(* Logix 5000 project; controller Hardy_1769_Sample_Program vendor 1 type 14 code 151 rev 30.11; software revision 30.02; part 3 of 5 *)
(* tags used below, declared in another part *)
   Default_Return_Float : HardyFloatWeight;   // Default Return Values With Weight In Foating Point Format
(* Hardy_HI1769_Scale_0, continued *)

ROUTINE Write_to_Non_Volatile   (* ladder *)
// Save Current Settings to Non-Volatile Memory
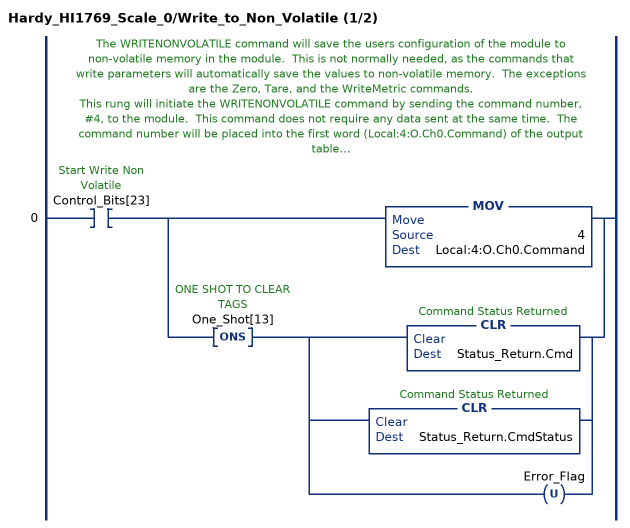
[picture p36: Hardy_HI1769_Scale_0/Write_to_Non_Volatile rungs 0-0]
   // The WRITENONVOLATILE command will save the users configuration of the module to non-volatile memory in the module.  This is not normally needed, as the commands that write parameters will automatically save the values to non-volatile memory.  The exceptions are the Zero, Tare, and the WriteMetric commands.
   // This rung will initiate the WRITENONVOLATILE command by sending the command number, #4, to the module.  This command does not require any data sent at the same time.  The command number will be placed into the first word (Local:4:O.Ch0.Command) of the output table.
   // Here the program will also clear the Status_Return tag and ERROR_FLAG of any previous values before running this command and receiving its return values.
   0: XIC(Control_Bits[23])[MOV(4,Local:4:O.Ch0.Command) ,ONS(One_Shot[13]) [CLR(Status_Return.Cmd) ,CLR(Status_Return.CmdStatus) ,OTU(Error_Flag) ] ];
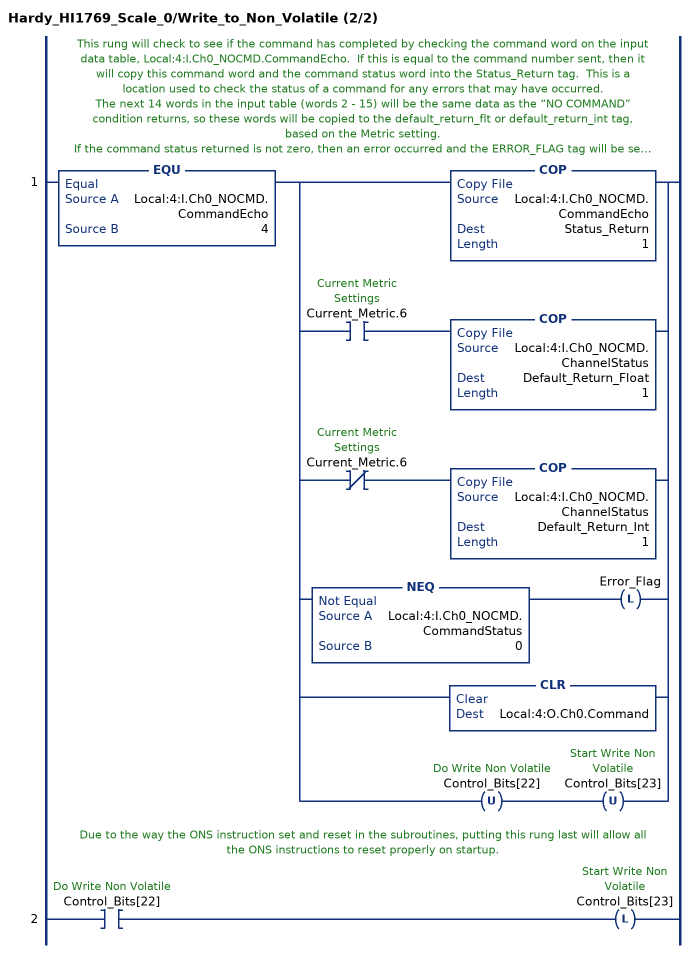
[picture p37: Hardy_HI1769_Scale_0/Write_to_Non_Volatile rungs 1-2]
   // This rung will check to see if the command has completed by checking the command word on the input data table, Local:4:I.Ch0_NOCMD.CommandEcho.  If this is equal to the command number sent, then it will copy this command word and the command status word into the Status_Return tag.  This is a location used to check the status of a command for any errors that may have occurred.
   // The next 14 words in the input table (words 2 - 15) will be the same data as the “NO COMMAND” condition returns, so these words will be copied to the default_return_flt or default_return_int tag, based on the Metric setting.
   // If the command status returned is not zero, then an error occurred and the ERROR_FLAG tag will be set high.  The user can monitor this bit to know if an error occurred and then check the Status_Return tag for the command and status return.
   // Finally, the command is cleared from the output table,Local:4:O.Ch0.Command, and any control bits are cleared.
   1: EQU(Local:4:I.Ch0_NOCMD.CommandEcho,4)[COP(Local:4:I.Ch0_NOCMD.CommandEcho,Status_Return,1) ,XIC(Current_Metric.6) COP(Local:4:I.Ch0_NOCMD.ChannelStatus,Default_Return_Float,1) ,XIO(Current_Metric.6) COP(Local:4:I.Ch0_NOCMD.ChannelStatus,Default_Return_Int,1) ,NEQ(Local:4:I.Ch0_NOCMD.CommandStatus,0) OTL(Error_Flag) ,CLR(Local:4:O.Ch0.Command) ,OTU(Control_Bits[22]) OTU(Control_Bits[23]) ];
   // Due to the way the ONS instruction set and reset in the subroutines, putting this rung last will allow all the ONS instructions to reset properly on startup.
   2: XIC(Control_Bits[22])OTL(Control_Bits[23]);
END_ROUTINE

ROUTINE Zero   (* ladder *)
// Zero Scale
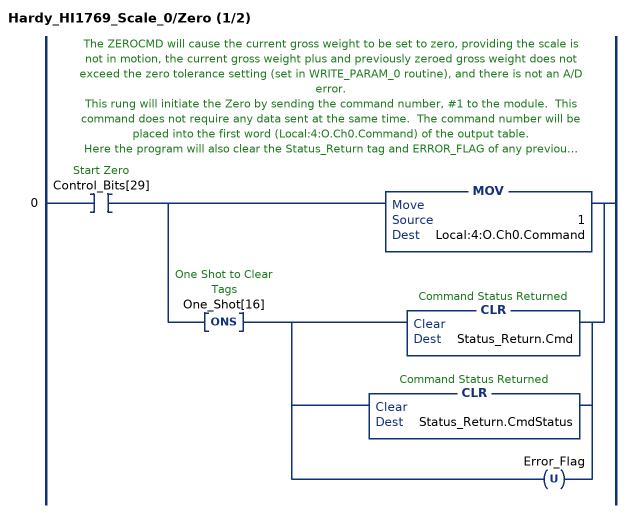
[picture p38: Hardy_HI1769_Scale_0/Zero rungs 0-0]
   // The ZEROCMD will cause the current gross weight to be set to zero, providing the scale is not in motion, the current gross weight plus and previously zeroed gross weight does not exceed the zero tolerance setting (set in WRITE_PARAM_0 routine), and there is not an A/D error.
   // This rung will initiate the Zero by sending the command number, #1 to the module.  This command does not require any data sent at the same time.  The command number will be placed into the first word (Local:4:O.Ch0.Command) of the output table.
   // Here the program will also clear the Status_Return tag and ERROR_FLAG of any previous values before running this command and receiving its return values.
   0: XIC(Control_Bits[29])[MOV(1,Local:4:O.Ch0.Command) ,ONS(One_Shot[16]) [CLR(Status_Return.Cmd) ,CLR(Status_Return.CmdStatus) ,OTU(Error_Flag) ] ];
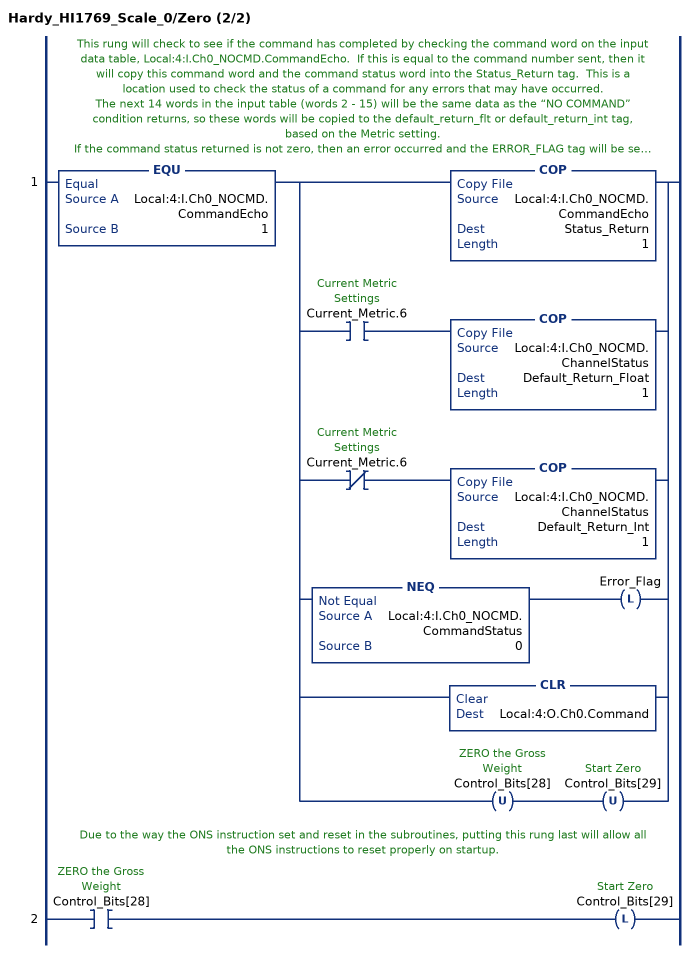
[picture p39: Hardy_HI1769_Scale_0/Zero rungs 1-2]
   // This rung will check to see if the command has completed by checking the command word on the input data table, Local:4:I.Ch0_NOCMD.CommandEcho.  If this is equal to the command number sent, then it will copy this command word and the command status word into the Status_Return tag.  This is a location used to check the status of a command for any errors that may have occurred.
   // The next 14 words in the input table (words 2 - 15) will be the same data as the “NO COMMAND” condition returns, so these words will be copied to the default_return_flt or default_return_int tag, based on the Metric setting.
   // If the command status returned is not zero, then an error occurred and the ERROR_FLAG tag will be set high.  The user can monitor this bit to know if an error occurred and then check the Status_Return tag for the command and status return.
   // Finally, the command is cleared from the output table, Local:4:O.Ch0.Command, and any control bits are cleared.
   1: EQU(Local:4:I.Ch0_NOCMD.CommandEcho,1)[COP(Local:4:I.Ch0_NOCMD.CommandEcho,Status_Return,1) ,XIC(Current_Metric.6) COP(Local:4:I.Ch0_NOCMD.ChannelStatus,Default_Return_Float,1) ,XIO(Current_Metric.6) COP(Local:4:I.Ch0_NOCMD.ChannelStatus,Default_Return_Int,1) ,NEQ(Local:4:I.Ch0_NOCMD.CommandStatus,0) OTL(Error_Flag) ,CLR(Local:4:O.Ch0.Command) ,OTU(Control_Bits[28]) OTU(Control_Bits[29]) ];
   // Due to the way the ONS instruction set and reset in the subroutines, putting this rung last will allow all the ONS instructions to reset properly on startup.
   2: XIC(Control_Bits[28])OTL(Control_Bits[29]);
END_ROUTINE
END_PROGRAM

PROGRAM Hardy_HI1769_Scale_1   (* main routine MainRoutine *)
VAR
   ADC_problem : BOOL;
   Control_Bits : BOOL[32] := ([30] := 1, [31] := 1);   // Control Bits For All Routines In This Program
        [11]   // Start Read Parameters 0
        [3]   // Start C2 Search
        [20]   // Do Write Metric
        [22]   // Do Write Non Volatile
        [10]   // Do Read Parameters 0
        [14]   // Do Read Serial Numbers
        [24]   // Do Write Parameters 0
        [16]   // Do Reload Non Volatile
        [26]   // Do Write Parameters 1
        [12]   // Do Read Parameters 1
        [23]   // Start Write Non Volatile
        [13]   // Start Read Parameters 1
        [21]   // Start Write Metric
        [7]   // Start CAL Low
        [19]   // Start Tare
        [29]   // Start Zero
        [1]   // Start C2 CAL
        [0]   // Do C2 CAL
        [5]   // Start CAL High
        [8]   // Set to Defaults
        [2]   // Do C2 Search
        [9]   // Start Defaults
        [15]   // Start Read Serial Numbers
        [25]   // Start Write Parameters 0
        [17]   // Start Reload Non Volatile
        [27]   // Starte Write Parameters 1
        [18]   // TARE the Net Weight
        [28]   // ZERO the Gross Weight
        [4]   // Do Traditional CAL HIGH
        [6]   // Do Traditional CAL LOW
   Control_Bits1 : BOOL[32];
        [4]   // Start Stability Test
        [3]   // Do Stability Test
        [5]   // Stop Stability Test
        [2]   // Read Test Data
        [1]   // Start IT Test
        [0]   // Do IT Test
   Current_Metric : INT := 2;   // Current Metric Settings
   Default_Return_Flt : HardyFloatWeight := (Channel_Status := 16#8040, Gross_Weight := -128.37949, Net_Weight := -128.37949, Metric := 16#0040, ADC_Counts := 1429576, Rate_of_Change := 514.0, Conv_Count := 32546);   // Default Return Values With Weight In Foating Point Format
   Default_Return_Int : HardyIntWeight := (Channel_Status := 16#8000, FirmwareRev := 16#0303, Metric := 16#0002, ADC_Counts := 2195901, Rate_of_Change := 1, Serial_Number := 4260, Conv_Count := 29766);   // Default Return Values With Weight In Integer Format
   Error_Flag : BOOL;
   Hardy_HI1769WS_Ch1_Channel_Status : INT := 16#8000;   // Ch1 Channel Status 16#0001 ADC Error 16#0002 AD Failure 16#0040 Motion 16#0080 Not Calibrated 16#0100 Eeprom Write 16#0200 Default Command Sent 16#8000 Ch Enabled
   Hardy_HI1769WS_Ch1_Command_Echo : INT;   // Ch1 Current Command Echo 16#0000 No Command 16#0001 Zero Command 16#0002 Tare Command 16#0003 Write Metric 16#0004 Write Non-Volatile 16#0010 Reload Non-Volatile 16#0064 Cal Low 16#0065 Cal High 16#0066 C2 Cal 16#0067 Write Param 0 16#0068 Write Param 1 16#0069 Read Param 0 16#006A Read Param 1 16#006B Stability Test 16#006C IT Test Results 16#006D Do IT Test 16#006E Search C2 16#006F IT Weigh Result 16#0070 C2 Serial 16#0094 Set Defaults 16#00FF Sofware Version
   Hardy_HI1769WS_Ch1_Command_Status : INT;   // Ch1 Current Command Status 0 Succes 1 ADC Error 2 ADC Failure 40 In Motion -3 Out of Tolerance -4 Out of Range -5 No Such Command -6 No C2 Device -7 C2 Unequal Caps -8 Hard Cal Not Enough Counts
   Hardy_HI1769WS_Ch1_Gross_Display_Float : REAL;   // Ch1 Gross Weight Float
   Hardy_HI1769WS_Ch1_Gross_Display_Int : DINT;   // Ch1 Gross Weight int
   Hardy_HI1769WS_Ch1_Last_Command : INT := 16#0064;   // Ch1 Last Command Sent 16#0000 No Command 16#0001 Zero Command 16#0002 Tare Command 16#0003 Write Metric 16#0004 Write Non-Volatile 16#0010 Reload Non-Volatile 16#0064 Cal Low 16#0065 Cal High 16#0066 C2 Cal 16#0067 Write Param 0 16#0068 Write Param 1 16#0069 Read Param 0 16#006A Read Param 1 16#006B Stability Test 16#006C IT Test Results 16#006D Do IT Test 16#006E Search C2 16#006F IT Weigh Result 16#0070 C2 Serial 16#0094 Set Defaults 16#00FF Sofware Version
   Hardy_HI1769WS_Ch1_Last_Command_Status : INT;   // Ch1 Last Command Status 0 Succes 1 ADC Error 2 ADC Failure 40 In Motion -3 Out of Tolerance -4 Out of Range -5 No Such Command -6 No C2 Device -7 C2 Unequal Caps -8 Hard Cal Not Enough Counts
   Hardy_HI1769WS_Ch1_Net_Display_Int : DINT;   // Ch1 Net Weight int
   Hardy_HiI1769WS_Ch1_Net_Display_Float : REAL;   // Ch1 Net Weight Float
   HI1769WS_Ch1_One_Decimal_Place_Float : REAL;   // One Decimal Place
   HI1769WS_Ch1_One_Decimal_Place_Int : DINT;
   HI1769WS_Ch1_Two_Decimal_Places_Int : DINT;
   HI1769WS_Ch1_Two_Decimals_Places_Float : REAL;   // Two Decimal Places
   IT_Float_Test : HardyFloatSysTest := (Cmd := 16#006d, NSensors := 4, CombinedGross := 24.86434, Gross1 := 5.319677, Gross2 := 5.8995957, Gross3 := 6.7579713, Gross4 := 6.8011603, InternalWgt := 822.809, JBOXWgt := 376.3745);   // IT Test Results in Float Format
   IT_Int_Test : HardyIntSysTest;   // IT Test Results In Int Format
   Metric : INT := 64;   // New Metric Setting
   Motion : BOOL;
   mV_Test_Results : HardySysTest2 := (Cmd := 16#006c, return_to_zero := 2#0000_0000_0001_1001, mvPerVCombined := 2053, mvPerV1 := 2332, mvPerV2 := 1887, mvPerV3 := 2135, mvPerV4 := 1816, SenseV := 46581, InputRes := 76);   // Results Second Part IT Test
   Number_of_Sensors : INT := 4;   // Number Of Sensors on System, Used For IT System Test
   One_Shot : BOOL[32];   // One Shots For Program Control
        [11]   // ONE SHOT TO CLEAR TAGS
        [13]   // ONE SHOT TO CLEAR TAGS
        [15]   // ONE SHOT TO CLEAR TAGS
        [17]   // ONE SHOT TO CLEAR TAGS
        [19]   // ONE SHOT TO CLEAR TAGS
        [10]   // ONE SHOT TO CLEAR TAGS
        [1]   // ONE SHOT TO CLEAR TAGS
        [3]   // ONE SHOT TO CLEAR TAGS
        [5]   // ONE SHOT TO CLEAR TAGS
        [7]   // ONE SHOT TO CLEAR TAGS
        [9]   // ONE SHOT TO CLEAR TAGS
        [0]   // ONE SHOT TO CLEAR TAGS
        [2]   // ONE SHOT TO CLEAR TAGS
        [16]   // ONE SHOT TO CLEAR TAGS
        [4]   // ONE SHOT TO CLEAR TAGS
        [6]   // ONE SHOT TO CLEAR TAGS
        [18]   // ONE SHOT TO CLEAR TAGS
        [12]   // ONE SHOT TO CLEAR TAGS
        [14]   // ONE SHOT TO CLEAR TAGS
        [8]   // ONE SHOT TO CLEAR TAGS
   Read_Float_Parameters_0 : HardyFloatParam0 := (ChanActive := 1, Metric := 16#0040, Waversaver := 2, NumAverages := 10, AutoZeroTol := 10.0, MotionTol := 3.0, ZeroTol := 3.0);   // Read Parameter 0 Values From Module Using Float Values
   Read_Float_Parameters_1 : HardyFloatParam1 := (SpanWeight := 5.0, ZeroCount := 1202223, CalZeroCount := 1202223, CalLowCount := 1202223, CalHighCount := 1191147);   // Read Parameter 1 Values From Module Using Float Values
   Read_Int_Parameters_0 : HardyIntParam0 := (ChanActive := 1, Metric := 16#0002, Waversaver := 3, NumAverages := 20, ROC_Time_Base := 10, AutoZeroTol := 1000, MotionTol := 500, ZeroTol := 1000);   // Read Parameter 0 Values From Module Using Int Values
   Read_Int_Parameters_1 : HardyIntParam1 := (SpanWeight := 600, CalLowWeight := 200, ZeroCount := 2399782, CalZeroCount := 2033102, CalLowCount := 2155320, CalHighCount := 2399757);   // Read Parameter 1 Values From Module Using Int Values
   Sensor_Select : INT := 1;   // Load Cell Selected For Reading Serial Number
   Serial_Number : HardyC2SerialNumber := (serialnumber[0] := '$00 ', serialnumber[1] := '$00 ', serialnumber[2] := '$001', serialnumber[3] := '$006', serialnumber[4] := '$004', serialnumber[5] := '$001', serialnumber[6] := '$009', serialnumber[7] := '$005', sensitivity := 30267, capacity := 150);   // Serial Number of Selected Load Cell Analog With Sensitivity and Capacity
   Signal_Select : INT := 1;   // Signal To Select For Stability Test
   Stability_Float : HardyFloatWeight := (Channel_Status := 16#8000, Gross_Weight := -1.7534312, Net_Weight := -1.7534312, Metric := 16#0040, ADC_Counts := 1125882, Rate_of_Change := 257.0, Conv_Count := 17903);   // Results Of Stability Test Float Format
   Stability_Int : HardyIntWeight;   // Results Of Stability Test Int Format
   Status_Return : HardyCmdResult := (Cmd := 16#0064);   // Command Status Returned
   Write_Float_Param_0 : HardyFloatParam0 := (ChanActive := 1, Metric := 16#0040, Waversaver := 2, NumAverages := 10, AutoZeroTol := 10.0, MotionTol := 3.0, ZeroTol := 3.0);   // New Parameter 0 Values In Float Format
   Write_Float_Param_1 : HardyFloatParam1 := (SpanWeight := 4.0);   // New Parameter 1 Values In Float Format
   Write_Int_Param_0 : HardyIntParam0 := (ChanActive := 1, Waversaver := 2, NumAverages := 20, AutoZeroTol := 10, MotionTol := 5, ZeroTol := 10);   // New Parameter 0 Value Int Format
   Write_Int_Param_1 : HardyIntParam1 := (TareWeight := 25, SpanWeight := 1000);   // New Parameter 1 Value Int Format
END_VAR

ROUTINE C2_Cal   (* ladder *)
// DO C2 CALIBRATION
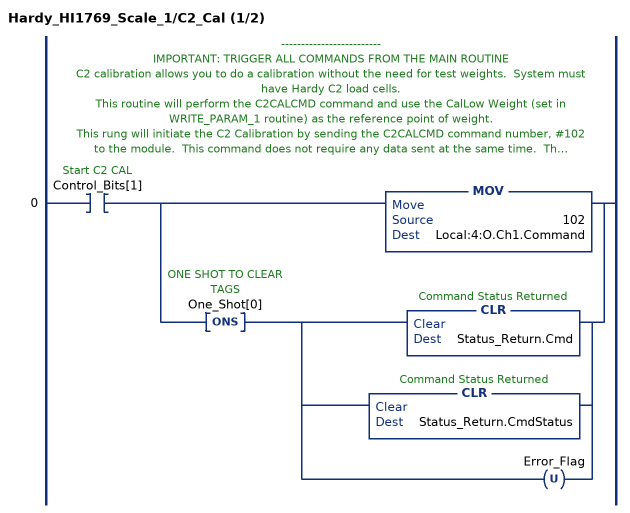
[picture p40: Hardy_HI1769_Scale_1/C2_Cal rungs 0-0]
   // -------------------------
   // IMPORTANT: TRIGGER ALL COMMANDS FROM THE MAIN ROUTINE
   // C2 calibration allows you to do a calibration without the need for test weights.  System must have Hardy C2 load cells.
   // This routine will perform the C2CALCMD command and use the CalLow Weight (set in WRITE_PARAM_1 routine) as the reference point of weight.
   // This rung will initiate the C2 Calibration by sending the C2CALCMD command number, #102 to the module.  This command does not require any data sent at the same time.  The command number will be placed into the first word (Local:1:O.Ch0.Command) of the output table.
   // Here the program will also clear the Status_Return tag and ERROR_FLAG of any previous values before running this command and receiving its return values.
   // IMPORTANT: TRIGGER ALL COMMANDS FROM THE MAIN ROUTINE
   // ------------------------------------------------------------------------------------------------------------------
   0: XIC(Control_Bits[1])[MOV(102,Local:4:O.Ch1.Command) ,ONS(One_Shot[0]) [CLR(Status_Return.Cmd) ,CLR(Status_Return.CmdStatus) ,OTU(Error_Flag) ] ];
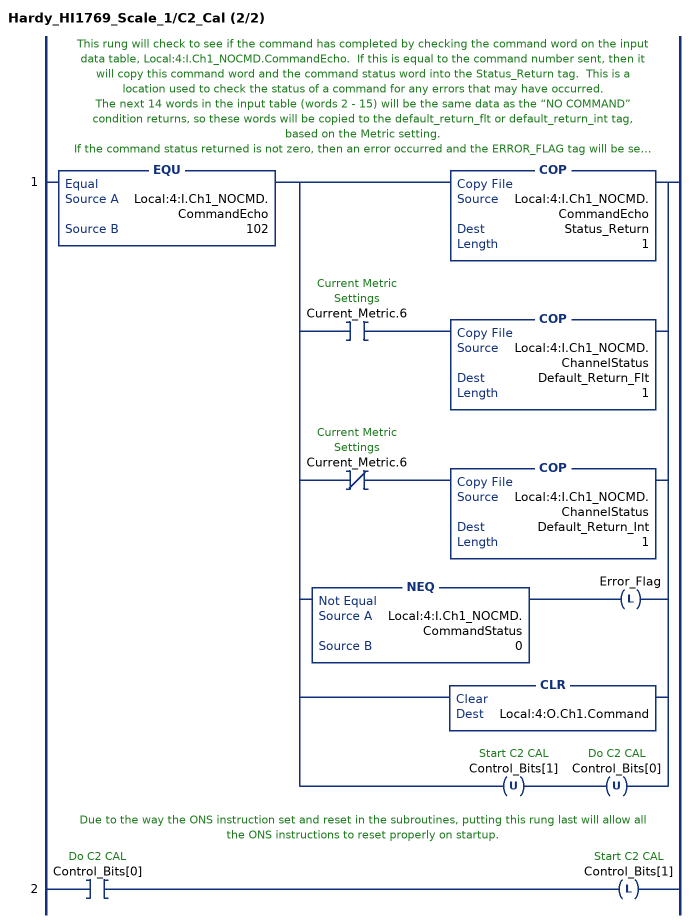
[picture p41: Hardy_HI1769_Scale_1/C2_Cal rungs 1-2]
   // This rung will check to see if the command has completed by checking the command word on the input data table, Local:4:I.Ch1_NOCMD.CommandEcho.  If this is equal to the command number sent, then it will copy this command word and the command status word into the Status_Return tag.  This is a location used to check the status of a command for any errors that may have occurred.
   // The next 14 words in the input table (words 2 - 15) will be the same data as the “NO COMMAND” condition returns, so these words will be copied to the default_return_flt or default_return_int tag, based on the Metric setting.
   // If the command status returned is not zero, then an error occurred and the ERROR_FLAG tag will be set high.  The user can monitor this bit to know if an error occurred and then check the Status_Return tag for the command and status return.
   // Finally, the command is cleared from the output table,Local:4:O.Ch1.Command, and any control bits are cleared.
   1: EQU(Local:4:I.Ch1_NOCMD.CommandEcho,102)[COP(Local:4:I.Ch1_NOCMD.CommandEcho,Status_Return,1) ,XIC(Current_Metric.6) COP(Local:4:I.Ch1_NOCMD.ChannelStatus,Default_Return_Flt,1) ,XIO(Current_Metric.6) COP(Local:4:I.Ch1_NOCMD.ChannelStatus,Default_Return_Int,1) ,NEQ(Local:4:I.Ch1_NOCMD.CommandStatus,0) OTL(Error_Flag) ,CLR(Local:4:O.Ch1.Command) ,OTU(Control_Bits[1]) OTU(Control_Bits[0]) ];
   // Due to the way the ONS instruction set and reset in the subroutines, putting this rung last will allow all the ONS instructions to reset properly on startup.
   2: XIC(Control_Bits[0])OTL(Control_Bits[1]);
END_ROUTINE

ROUTINE C2_Search   (* ladder *)
// CHECK FOR NUMBER OF C2 LOAD CELLS ON SYSTEM
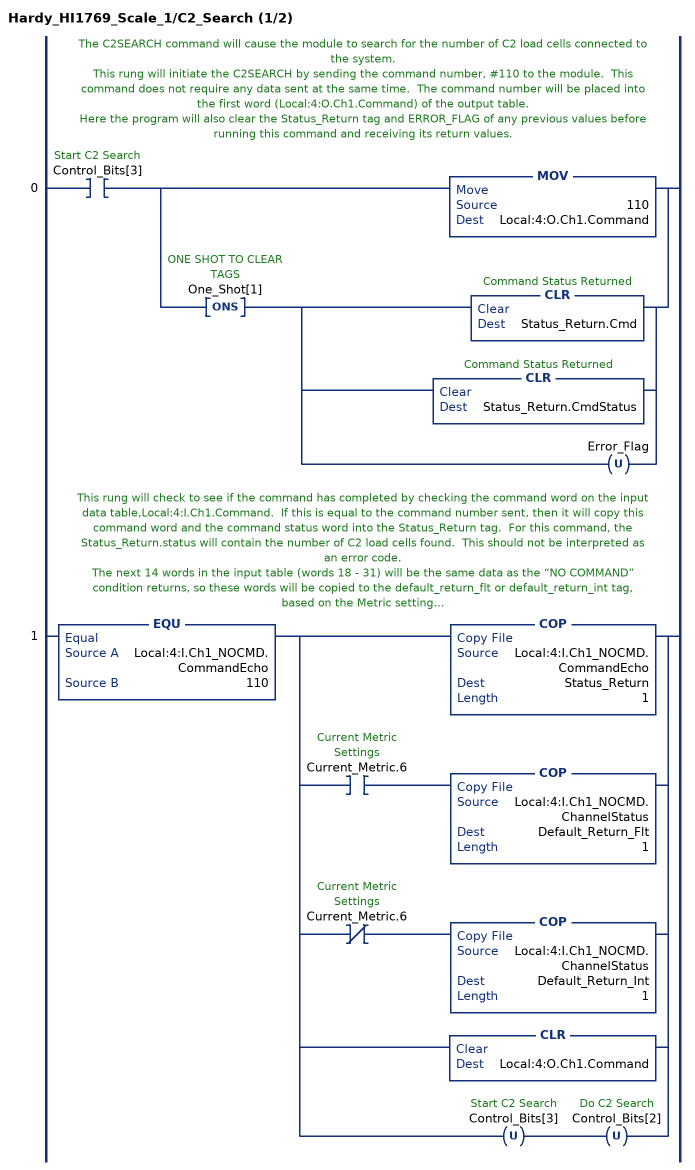
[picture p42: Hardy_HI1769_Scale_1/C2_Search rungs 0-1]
   // The C2SEARCH command will cause the module to search for the number of C2 load cells connected to the system.
   // This rung will initiate the C2SEARCH by sending the command number, #110 to the module.  This command does not require any data sent at the same time.  The command number will be placed into the first word (Local:4:O.Ch1.Command) of the output table.
   // Here the program will also clear the Status_Return tag and ERROR_FLAG of any previous values before running this command and receiving its return values.
   0: XIC(Control_Bits[3])[MOV(110,Local:4:O.Ch1.Command) ,ONS(One_Shot[1]) [CLR(Status_Return.Cmd) ,CLR(Status_Return.CmdStatus) ,OTU(Error_Flag) ] ];
   // This rung will check to see if the command has completed by checking the command word on the input data table,Local:4:I.Ch1.Command.  If this is equal to the command number sent, then it will copy this command word and the command status word into the Status_Return tag.  For this command, the Status_Return.status will contain the number of C2 load cells found.  This should not be interpreted as an error code.
   // The next 14 words in the input table (words 18 - 31) will be the same data as the “NO COMMAND” condition returns, so these words will be copied to the default_return_flt or default_return_int tag, based on the Metric setting.
   // Finally, the command is cleared from the output table,Local:4:O.Ch1.Command, and any control bits are cleared.
   1: EQU(Local:4:I.Ch1_NOCMD.CommandEcho,110)[COP(Local:4:I.Ch1_NOCMD.CommandEcho,Status_Return,1) ,XIC(Current_Metric.6) COP(Local:4:I.Ch1_NOCMD.ChannelStatus,Default_Return_Flt,1) ,XIO(Current_Metric.6) COP(Local:4:I.Ch1_NOCMD.ChannelStatus,Default_Return_Int,1) ,CLR(Local:4:O.Ch1.Command) ,OTU(Control_Bits[3]) OTU(Control_Bits[2]) ];
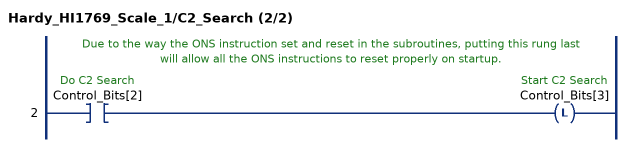
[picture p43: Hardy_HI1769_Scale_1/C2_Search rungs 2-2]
   // Due to the way the ONS instruction set and reset in the subroutines, putting this rung last will allow all the ONS instructions to reset properly on startup.
   2: XIC(Control_Bits[2])OTL(Control_Bits[3]);
END_ROUTINE

ROUTINE Cal_High   (* ladder *)
// DO HIGH POINT IN HARD CALIBRATION
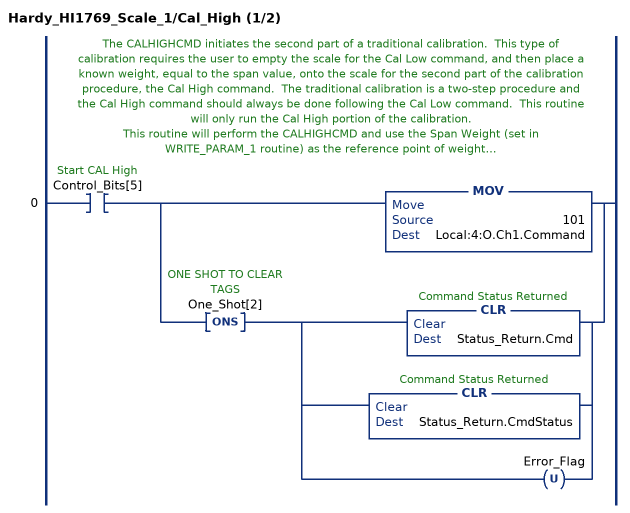
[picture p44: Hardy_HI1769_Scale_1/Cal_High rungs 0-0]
   // The CALHIGHCMD initiates the second part of a traditional calibration.  This type of calibration requires the user to empty the scale for the Cal Low command, and then place a known weight, equal to the span value, onto the scale for the second part of the calibration procedure, the Cal High command.  The traditional calibration is a two-step procedure and the Cal High command should always be done following the Cal Low command.  This routine will only run the Cal High portion of the calibration.
   // This routine will perform the CALHIGHCMD and use the Span Weight (set in WRITE_PARAM_1 routine) as the reference point of weight.
   // NOTE:  User must have the weight on the scale prior to initiating this command.
   // This rung will initiate the Cal High by sending the Cal High command number, #101 to the module.  This command does not require any data sent at the same time.  The command number will be placed into the first word (Local:4:O.Ch1.Command) of the output table.
   // Here the program will also clear the Status_Return tag and ERROR_FLAG of any previous values before running this command and receiving its return values.
   0: XIC(Control_Bits[5])[MOV(101,Local:4:O.Ch1.Command) ,ONS(One_Shot[2]) [CLR(Status_Return.Cmd) ,CLR(Status_Return.CmdStatus) ,OTU(Error_Flag) ] ];
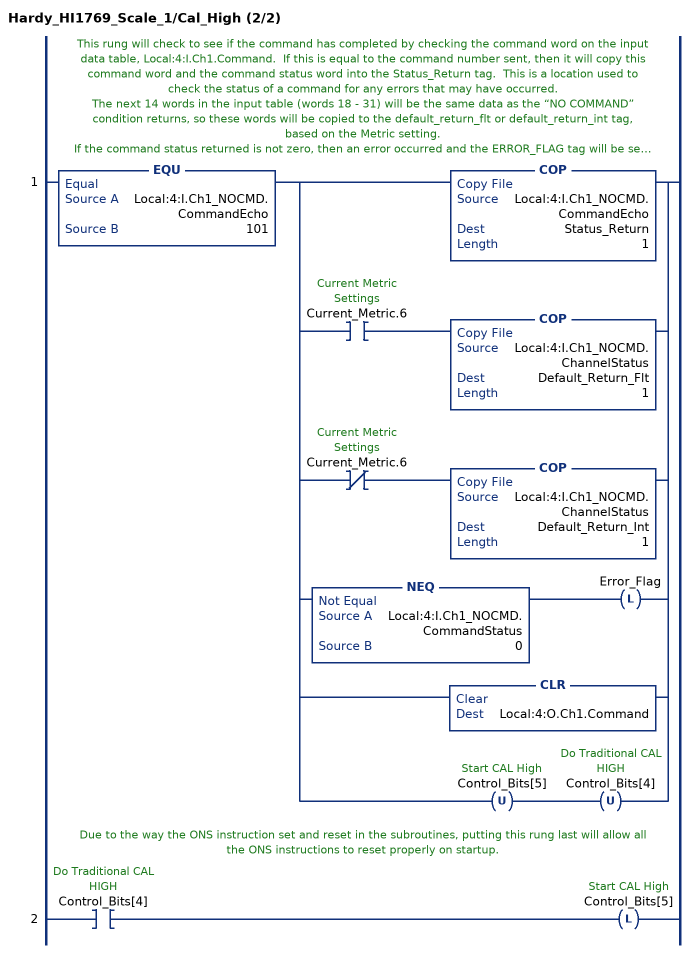
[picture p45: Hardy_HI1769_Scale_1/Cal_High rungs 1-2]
   // This rung will check to see if the command has completed by checking the command word on the input data table, Local:4:I.Ch1.Command.  If this is equal to the command number sent, then it will copy this command word and the command status word into the Status_Return tag.  This is a location used to check the status of a command for any errors that may have occurred.
   // The next 14 words in the input table (words 18 - 31) will be the same data as the “NO COMMAND” condition returns, so these words will be copied to the default_return_flt or default_return_int tag, based on the Metric setting.
   // If the command status returned is not zero, then an error occurred and the ERROR_FLAG tag will be set high.  The user can monitor this bit to know if an error occurred and then check the Status_Return tag for the command and status return.
   // Finally, the command is cleared from the output table, Local:4:O.Ch1.Command, and any control bits are cleared.
   1: EQU(Local:4:I.Ch1_NOCMD.CommandEcho,101)[COP(Local:4:I.Ch1_NOCMD.CommandEcho,Status_Return,1) ,XIC(Current_Metric.6) COP(Local:4:I.Ch1_NOCMD.ChannelStatus,Default_Return_Flt,1) ,XIO(Current_Metric.6) COP(Local:4:I.Ch1_NOCMD.ChannelStatus,Default_Return_Int,1) ,NEQ(Local:4:I.Ch1_NOCMD.CommandStatus,0) OTL(Error_Flag) ,CLR(Local:4:O.Ch1.Command) ,OTU(Control_Bits[5]) OTU(Control_Bits[4]) ];
   // Due to the way the ONS instruction set and reset in the subroutines, putting this rung last will allow all the ONS instructions to reset properly on startup.
   2: XIC(Control_Bits[4])OTL(Control_Bits[5]);
END_ROUTINE

ROUTINE Cal_Low   (* ladder *)
// DO LOW POINT OF HARD CALIBRATION
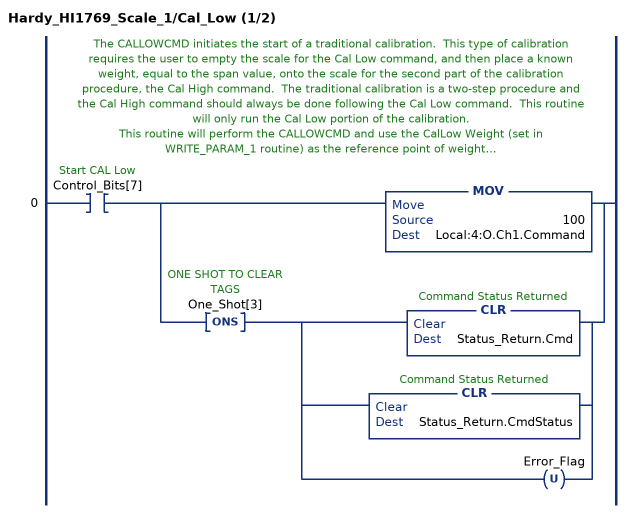
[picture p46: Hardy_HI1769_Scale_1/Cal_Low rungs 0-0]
   // The CALLOWCMD initiates the start of a traditional calibration.  This type of calibration requires the user to empty the scale for the Cal Low command, and then place a known weight, equal to the span value, onto the scale for the second part of the calibration procedure, the Cal High command.  The traditional calibration is a two-step procedure and the Cal High command should always be done following the Cal Low command.  This routine will only run the Cal Low portion of the calibration.
   // This routine will perform the CALLOWCMD and use the CalLow Weight (set in WRITE_PARAM_1 routine) as the reference point of weight.
   // This rung will initiate the Cal Low by sending the Cal Low command number, #100 to the module.  This command does not require any data sent at the same time.  The command number will be placed into the first word (Local:4:O.Ch1.Command) of the output table.
   // Here the program will also clear the Status_Return tag and ERROR_FLAG of any previous values before running this command and receiving its return values.
   0: XIC(Control_Bits[7])[MOV(100,Local:4:O.Ch1.Command) ,ONS(One_Shot[3]) [CLR(Status_Return.Cmd) ,CLR(Status_Return.CmdStatus) ,OTU(Error_Flag) ] ];
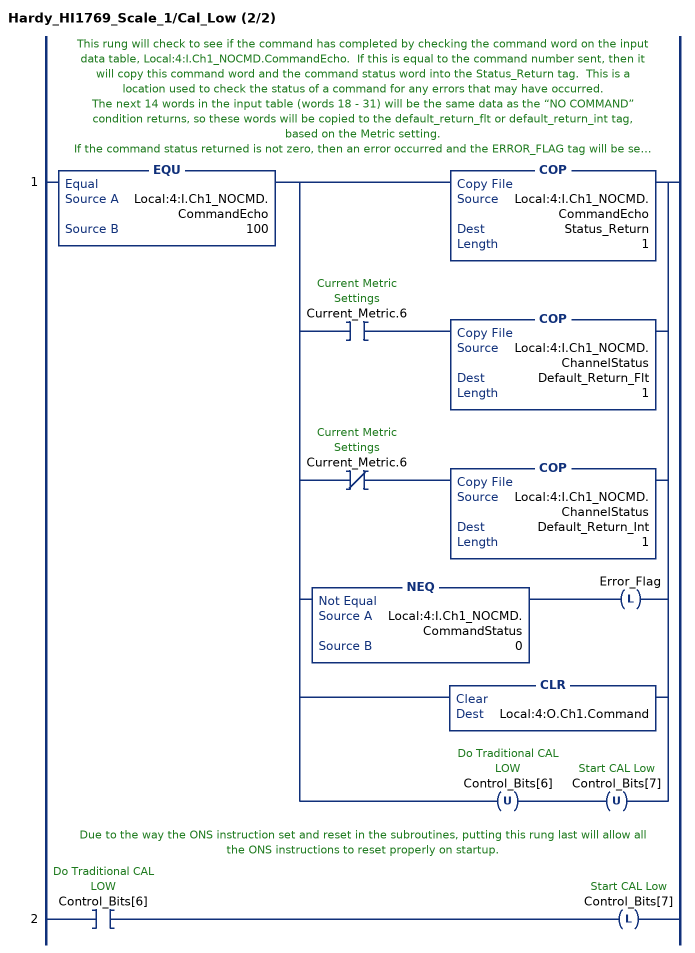
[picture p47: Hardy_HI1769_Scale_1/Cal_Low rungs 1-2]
   // This rung will check to see if the command has completed by checking the command word on the input data table, Local:4:I.Ch1_NOCMD.CommandEcho.  If this is equal to the command number sent, then it will copy this command word and the command status word into the Status_Return tag.  This is a location used to check the status of a command for any errors that may have occurred.
   // The next 14 words in the input table (words 18 - 31) will be the same data as the “NO COMMAND” condition returns, so these words will be copied to the default_return_flt or default_return_int tag, based on the Metric setting.
   // If the command status returned is not zero, then an error occurred and the ERROR_FLAG tag will be set high.  The user can monitor this bit to know if an error occurred and then check the Status_Return tag for the command and status return.
   // Finally, the command is cleared from the output table, Local:4:O.Ch1.Command, and any control bits are cleared.
   1: EQU(Local:4:I.Ch1_NOCMD.CommandEcho,100)[COP(Local:4:I.Ch1_NOCMD.CommandEcho,Status_Return,1) ,XIC(Current_Metric.6) COP(Local:4:I.Ch1_NOCMD.ChannelStatus,Default_Return_Flt,1) ,XIO(Current_Metric.6) COP(Local:4:I.Ch1_NOCMD.ChannelStatus,Default_Return_Int,1) ,NEQ(Local:4:I.Ch1_NOCMD.CommandStatus,0) OTL(Error_Flag) ,CLR(Local:4:O.Ch1.Command) ,OTU(Control_Bits[6]) OTU(Control_Bits[7]) ];
   // Due to the way the ONS instruction set and reset in the subroutines, putting this rung last will allow all the ONS instructions to reset properly on startup.
   2: XIC(Control_Bits[6])OTL(Control_Bits[7]);
END_ROUTINE

ROUTINE Defaults   (* ladder *)
// SETS MODULE BACK TO DEFAULT SETTINGS
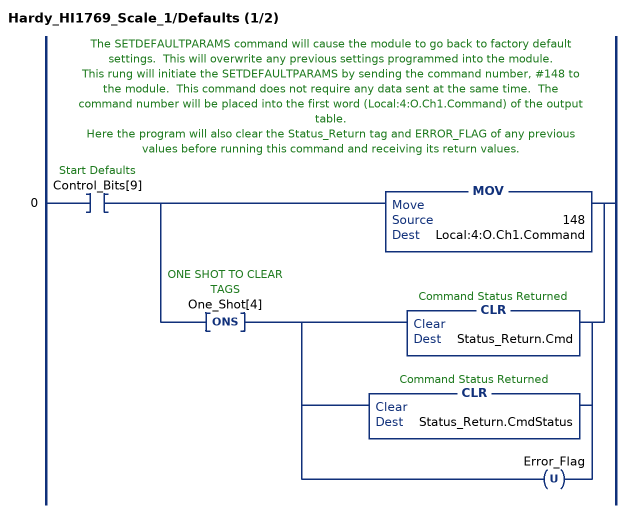
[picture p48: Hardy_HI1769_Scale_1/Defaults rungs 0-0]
   // The SETDEFAULTPARAMS command will cause the module to go back to factory default settings.  This will overwrite any previous settings programmed into the module.
   // This rung will initiate the SETDEFAULTPARAMS by sending the command number, #148 to the module.  This command does not require any data sent at the same time.  The command number will be placed into the first word (Local:4:O.Ch1.Command) of the output table.
   // Here the program will also clear the Status_Return tag and ERROR_FLAG of any previous values before running this command and receiving its return values.
   0: XIC(Control_Bits[9])[MOV(148,Local:4:O.Ch1.Command) ,ONS(One_Shot[4]) [CLR(Status_Return.Cmd) ,CLR(Status_Return.CmdStatus) ,OTU(Error_Flag) ] ];
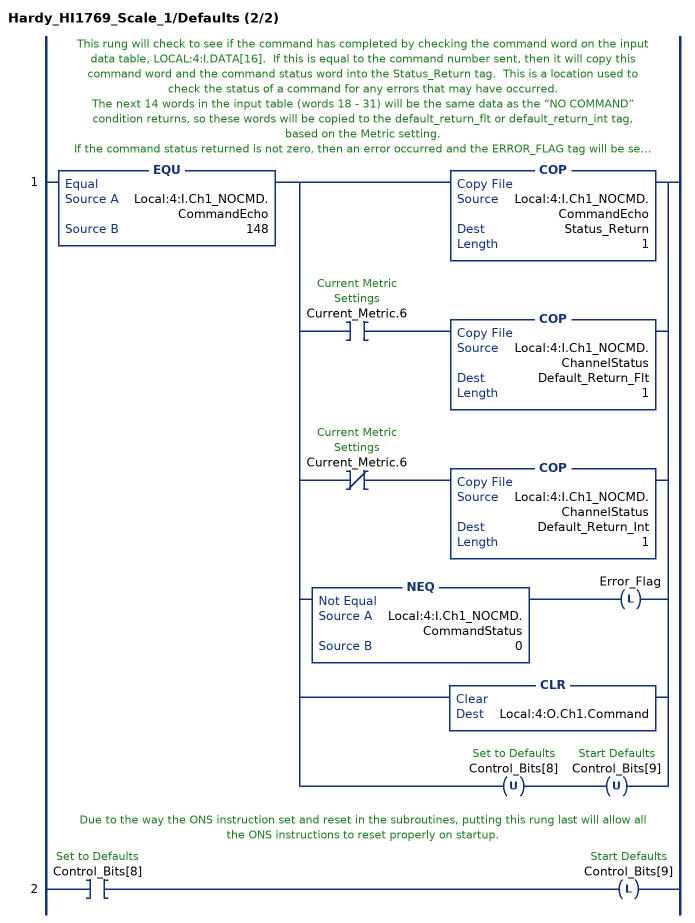
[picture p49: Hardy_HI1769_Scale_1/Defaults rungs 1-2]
   // This rung will check to see if the command has completed by checking the command word on the input data table, LOCAL:4:I.DATA[16].  If this is equal to the command number sent, then it will copy this command word and the command status word into the Status_Return tag.  This is a location used to check the status of a command for any errors that may have occurred.
   // The next 14 words in the input table (words 18 - 31) will be the same data as the “NO COMMAND” condition returns, so these words will be copied to the default_return_flt or default_return_int tag, based on the Metric setting.
   // If the command status returned is not zero, then an error occurred and the ERROR_FLAG tag will be set high.  The user can monitor this bit to know if an error occurred and then check the Status_Return tag for the command and status return.
   // Finally, the command is cleared from the output table, Local:4:O.Ch0.Command, and any control bits are cleared.
   1: EQU(Local:4:I.Ch1_NOCMD.CommandEcho,148)[COP(Local:4:I.Ch1_NOCMD.CommandEcho,Status_Return,1) ,XIC(Current_Metric.6) COP(Local:4:I.Ch1_NOCMD.ChannelStatus,Default_Return_Flt,1) ,XIO(Current_Metric.6) COP(Local:4:I.Ch1_NOCMD.ChannelStatus,Default_Return_Int,1) ,NEQ(Local:4:I.Ch1_NOCMD.CommandStatus,0) OTL(Error_Flag) ,CLR(Local:4:O.Ch1.Command) ,OTU(Control_Bits[8]) OTU(Control_Bits[9]) ];
   // Due to the way the ONS instruction set and reset in the subroutines, putting this rung last will allow all the ONS instructions to reset properly on startup.
   2: XIC(Control_Bits[8])OTL(Control_Bits[9]);
END_ROUTINE

ROUTINE IT_Test   (* ladder *)
// RUN WEIGH SYSTEM TEST
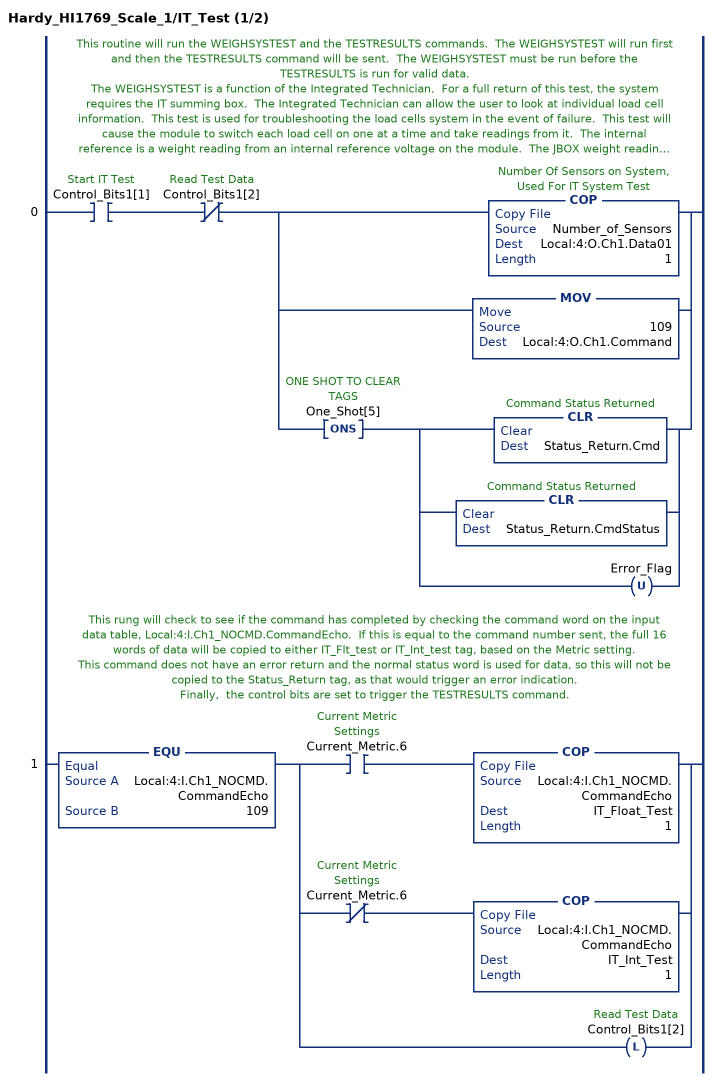
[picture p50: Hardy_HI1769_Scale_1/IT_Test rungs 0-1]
   // This routine will run the WEIGHSYSTEST and the TESTRESULTS commands.  The WEIGHSYSTEST will run first and then the TESTRESULTS command will be sent.  The WEIGHSYSTEST must be run before the TESTRESULTS is run for valid data.
   // The WEIGHSYSTEST is a function of the Integrated Technician.  For a full return of this test, the system requires the IT summing box.  The Integrated Technician can allow the user to look at individual load cell information.  This test is used for troubleshooting the load cells system in the event of failure.  This test will cause the module to switch each load cell on one at a time and take readings from it.  The internal reference is a weight reading from an internal reference voltage on the module.  The JBOX weight reading is from a reference voltage on the JBOX.
   // When the system is equipped with the IT summing box, this test will return the following information to:
   // **Local Tags IT_Float_Test or Local Tags IT_Int depending on Metrix bit 6**
   // Word 0 = Command Number - 109
   // Word 1 = Number of sensors - as entered in the command
   // Word 2 = Combined gross weight LSW - Gross weight from all load cells
   // Word 3 = Combined gross weight MSW - Gross weight from all load cells
   // Word 4 = Gross weight load cell number 1 LSW - Individual weight from load cell #1
   // Word 5 = Gross weight load cell number 1 MSW - Individual weight from load cell #1
   // Word 6 = Gross weight load cell number 2 LSW - Individual weight from load cell #2
   // Word 7 = Gross weight load cell number 2 MSW - Individual weight from load cell #2
   // Word 8 = Gross weight load cell number 3 LSW - Individual weight from load cell #3
   // Word 9 = Gross weight load cell number 3 MSW - Individual weight from load cell #3
   // Word 10 = Gross weight load cell number 4 LSW - Individual weight from load cell #4
   // Word 11 = Gross weight load cell number 4 MSW - Individual weight from load cell #4
   // Word 12 = Internal reference LSW - Weight reading from internal reference voltage
   // Word 13 = Internal reference MSW - Weight reading from internal reference voltage
   // Word 14 = Jbox reference weight LSW - Weight reading from JBOX reference voltage
   // Word 15 = Jbox reference weight MSW - Weight reading from JBOX reference voltage
   // Words 2-15 are weight values, scaled according to the current Metric parameter value.
   // NOTES:
   // **The word locations in the input table will have the names as used for the default return, and those names will not apply to the return values for this command. So the copy
   // command in the next rung will copy the data into a UDT with the proper names for the data.  Users should reference these UDTs for the data instead of the input tables.**
   // **If system has fewer than four load cells, then only the readings from those load cells will be valid, and unused load cell positions should be ignored.**
   // **If the system does not have the IT summing box, then the only valid returns will be the internal reference and the combined readings.**
   // This rung will initiate the WEIGHSYSTEST by sending the command number, 109, and the number of load cells, from Number_of_Sensors tag, into the output table at Local:1:O.Ch1.Command and Local:1:O.Ch1.Data01.
   // Here the program will also clear the Status_Return tag and ERROR_FLAG of any previous values before running this command and receiving its return values.
   0: XIC(Control_Bits1[1])XIO(Control_Bits1[2])[COP(Number_of_Sensors,Local:4:O.Ch1.Data01,1) ,MOV(109,Local:4:O.Ch1.Command) ,ONS(One_Shot[5]) [CLR(Status_Return.Cmd) ,CLR(Status_Return.CmdStatus) ,OTU(Error_Flag) ] ];
   // This rung will check to see if the command has completed by checking the command word on the input data table, Local:4:I.Ch1_NOCMD.CommandEcho.  If this is equal to the command number sent, the full 16 words of data will be copied to either IT_Flt_test or IT_Int_test tag, based on the Metric setting.
   // This command does not have an error return and the normal status word is used for data, so this will not be copied to the Status_Return tag, as that would trigger an error indication.
   // Finally,  the control bits are set to trigger the TESTRESULTS command.
   1: EQU(Local:4:I.Ch1_NOCMD.CommandEcho,109)[XIC(Current_Metric.6) COP(Local:4:I.Ch1_NOCMD.CommandEcho,IT_Float_Test,1) ,XIO(Current_Metric.6) COP(Local:4:I.Ch1_NOCMD.CommandEcho,IT_Int_Test,1) ,OTL(Control_Bits1[2]) ];
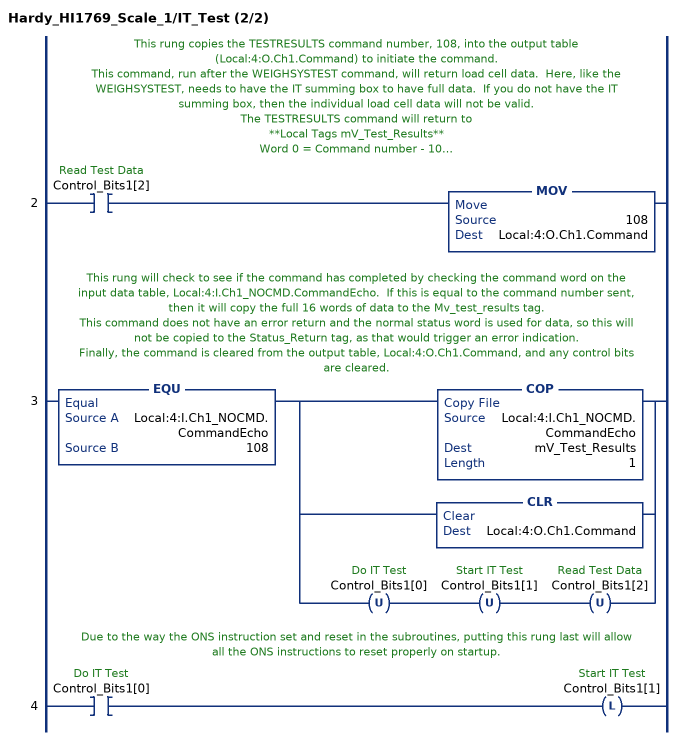
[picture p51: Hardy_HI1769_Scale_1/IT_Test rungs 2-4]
   // This rung copies the TESTRESULTS command number, 108, into the output table (Local:4:O.Ch1.Command) to initiate the command.
   // This command, run after the WEIGHSYSTEST command, will return load cell data.  Here, like the WEIGHSYSTEST, needs to have the IT summing box to have full data.  If you do not have the IT summing box, then the individual load cell data will not be valid.
   // The TESTRESULTS command will return to
   // **Local Tags mV_Test_Results**
   // Word 0 = Command number - 108
   // Word 1 = Return to Zero test. Return to Zero test results are bit coded.  Bits set to 1 indicate Non-Return to Zero.
   //      Bit 0 = Combined Weight
   //      Bit 1 = Load Cell #1 (IT JBOX only)
   //      Bit 2 = Load Cell #2 (IT JBOX only)
   //      Bit 3 = Load Cell #3 (IT JBOX only)
   //      Bit 4 = Load Cell #4 (IT JBOX only)
   // Word 2 = Mv/V Combined LSW - Millivolts/Volt return from all Load Cells combined.
   // Word 3 = Mv/VCombined MSW - Millivolts/Volt return from all Load Cells combined.
   // Word 4 = Mv/V Load Cell #1 LSW - Millivolts/Volt return from Load Cell #1
   // Word 5 = Mv/V Load Cell #1 MSW - Millivolts/Volt return from Load Cell #1
   // Word 6 = Mv/V load cell #2 LSW - Millivolts/Volt return from Load Cell #2
   // Word 7 = Mv/V Load Cell #2 MSW - Millivolts/Volt return from Load Cell #2
   // Word 8 = Mv/V Load Cell #3 LSW - Millivolts/Volt return from Load Cell #3
   // Word 9 = Mv/V Load Cell #3 MSW - Millivolts/Volt return from Load Cell #3
   // Word 10 = Mv/V Load Cell #4 LSW - Millivolts/Volt return from Load Cell #4
   // Word 11 = Mv/V Load Cell #4 MSW - Millivolts/Volt return from Load Cell #4
   // Word 12 = Sense Volts, LSW - Voltage on the Sense Lines
   // Word 13 = Sense Volts, MSW - Voltage on the Sense Lines
   // Word 14 = Resistance LSW - Load Cell input resistance determined from C2 at last calibration
   // Word 15 = Resistance MSW - Load Cell input resistance determined from C2 at last calibration
   // Note:
   // **Words 2-15 are all INTEGER values.  Millivolt/volt readings have 4 decimal places.**
   // **Load cell resistance has zero decimal places.  Sense volts has 2 decimal placed.**
   2: XIC(Control_Bits1[2])MOV(108,Local:4:O.Ch1.Command);
   // This rung will check to see if the command has completed by checking the command word on the input data table, Local:4:I.Ch1_NOCMD.CommandEcho.  If this is equal to the command number sent, then it will copy the full 16 words of data to the Mv_test_results tag.
   // This command does not have an error return and the normal status word is used for data, so this will not be copied to the Status_Return tag, as that would trigger an error indication.
   // Finally, the command is cleared from the output table, Local:4:O.Ch1.Command, and any control bits are cleared.
   3: EQU(Local:4:I.Ch1_NOCMD.CommandEcho,108)[COP(Local:4:I.Ch1_NOCMD.CommandEcho,mV_Test_Results,1) ,CLR(Local:4:O.Ch1.Command) ,OTU(Control_Bits1[0]) OTU(Control_Bits1[1]) OTU(Control_Bits1[2]) ];
   // Due to the way the ONS instruction set and reset in the subroutines, putting this rung last will allow all the ONS instructions to reset properly on startup.
   4: XIC(Control_Bits1[0])OTL(Control_Bits1[1]);
END_ROUTINE

ROUTINE MainRoutine   (* ladder *)
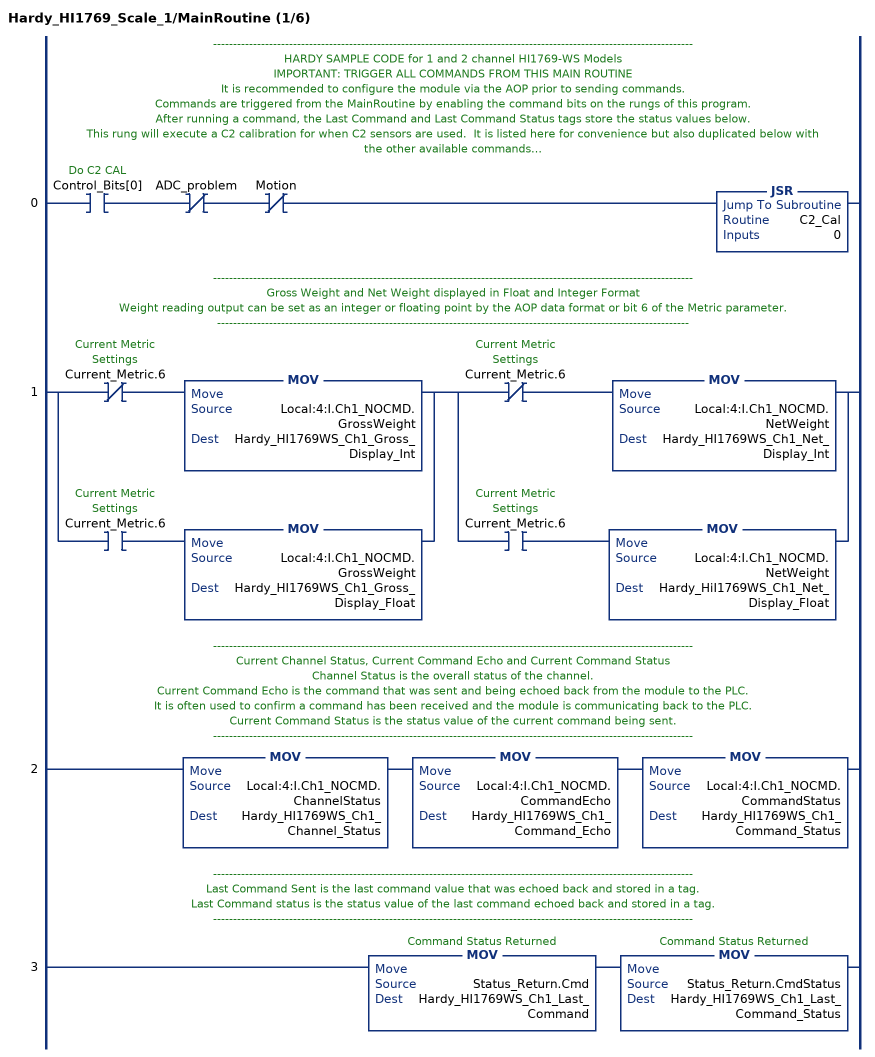
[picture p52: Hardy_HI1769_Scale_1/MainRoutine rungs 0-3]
   // ------------------------------------------------------------------------------------------------------------------------
   // HARDY SAMPLE CODE for 1 and 2 channel HI1769-WS Models
   // IMPORTANT: TRIGGER ALL COMMANDS FROM THIS MAIN ROUTINE
   // It is recommended to configure the module via the AOP prior to sending commands.
   // Commands are triggered from the MainRoutine by enabling the command bits on the rungs of this program.
   // After running a command, the Last Command and Last Command Status tags store the status values below.
   // This rung will execute a C2 calibration for when C2 sensors are used.  It is listed here for convenience but also duplicated below with the other available commands.
   // This rung is conditioned with the ADC problem (often a wiring issue or a damaged cell) and Motion bit.  If either of these conditions is present, the command fails and returns a Command Status.
   // IMPORTANT: TRIGGER ALL COMMANDS FROM THIS MAIN ROUTINE
   // ------------------------------------------------------------------------------------------------------------------------
   0: XIC(Control_Bits[0])XIO(ADC_problem)XIO(Motion)JSR(C2_Cal,0);
   // ------------------------------------------------------------------------------------------------------------------------
   // Gross Weight and Net Weight displayed in Float and Integer Format
   // Weight reading output can be set as an integer or floating point by the AOP data format or bit 6 of the Metric parameter.
   // ----------------------------------------------------------------------------------------------------------------------
   1: [XIO(Current_Metric.6) MOV(Local:4:I.Ch1_NOCMD.GrossWeight,Hardy_HI1769WS_Ch1_Gross_Display_Int) ,XIC(Current_Metric.6) MOV(Local:4:I.Ch1_NOCMD.GrossWeight,Hardy_HI1769WS_Ch1_Gross_Display_Float) ][XIO(Current_Metric.6) MOV(Local:4:I.Ch1_NOCMD.NetWeight,Hardy_HI1769WS_Ch1_Net_Display_Int) ,XIC(Current_Metric.6) MOV(Local:4:I.Ch1_NOCMD.NetWeight,Hardy_HiI1769WS_Ch1_Net_Display_Float) ];
   // ------------------------------------------------------------------------------------------------------------------------
   // Current Channel Status, Current Command Echo and Current Command Status
   // Channel Status is the overall status of the channel.
   // Current Command Echo is the command that was sent and being echoed back from the module to the PLC.
   // It is often used to confirm a command has been received and the module is communicating back to the PLC.
   // Current Command Status is the status value of the current command being sent.
   // ------------------------------------------------------------------------------------------------------------------------
   2: MOV(Local:4:I.Ch1_NOCMD.ChannelStatus,Hardy_HI1769WS_Ch1_Channel_Status)MOV(Local:4:I.Ch1_NOCMD.CommandEcho,Hardy_HI1769WS_Ch1_Command_Echo)MOV(Local:4:I.Ch1_NOCMD.CommandStatus,Hardy_HI1769WS_Ch1_Command_Status);
   // ------------------------------------------------------------------------------------------------------------------------
   // Last Command Sent is the last command value that was echoed back and stored in a tag.
   // Last Command status is the status value of the last command echoed back and stored in a tag.
   // ------------------------------------------------------------------------------------------------------------------------
   3: MOV(Status_Return.Cmd,Hardy_HI1769WS_Ch1_Last_Command)MOV(Status_Return.CmdStatus,Hardy_HI1769WS_Ch1_Last_Command_Status);
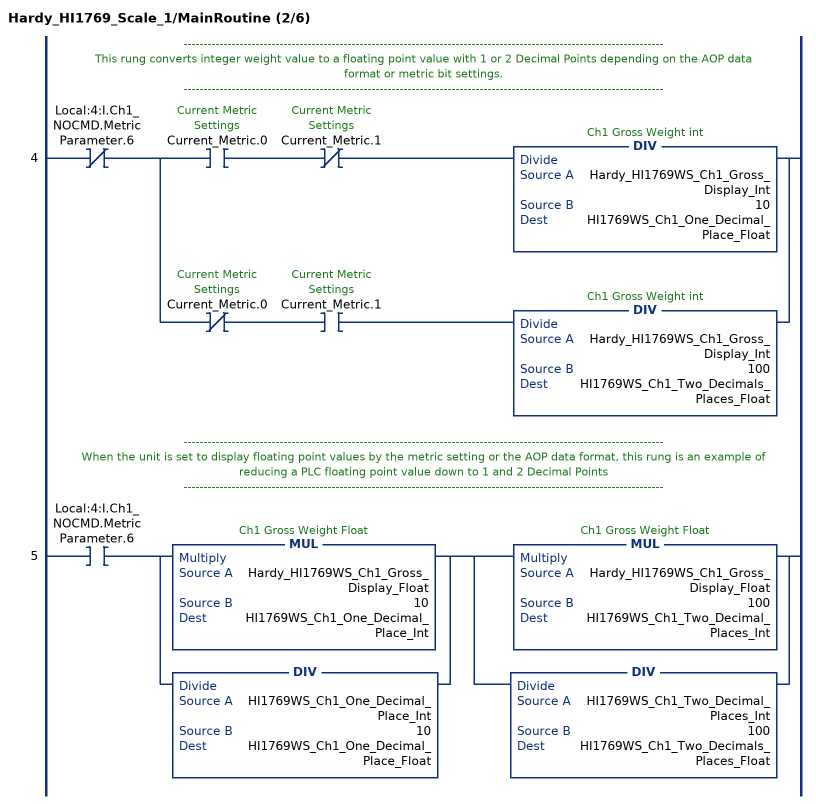
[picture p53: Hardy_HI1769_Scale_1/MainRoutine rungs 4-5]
   // ------------------------------------------------------------------------------------------------------------------------
   // This rung converts integer weight value to a floating point value with 1 or 2 Decimal Points depending on the AOP data format or metric bit settings.
   // ------------------------------------------------------------------------------------------------------------------------
   4: XIO(Local:4:I.Ch1_NOCMD.MetricParameter.6)[XIC(Current_Metric.0) XIO(Current_Metric.1) DIV(Hardy_HI1769WS_Ch1_Gross_Display_Int,10,HI1769WS_Ch1_One_Decimal_Place_Float) ,XIO(Current_Metric.0) XIC(Current_Metric.1) DIV(Hardy_HI1769WS_Ch1_Gross_Display_Int,100,HI1769WS_Ch1_Two_Decimals_Places_Float) ];
   // ------------------------------------------------------------------------------------------------------------------------
   // When the unit is set to display floating point values by the metric setting or the AOP data format, this rung is an example of reducing a PLC floating point value down to 1 and 2 Decimal Points
   // ------------------------------------------------------------------------------------------------------------------------
   5: XIC(Local:4:I.Ch1_NOCMD.MetricParameter.6)[MUL(Hardy_HI1769WS_Ch1_Gross_Display_Float,10,HI1769WS_Ch1_One_Decimal_Place_Int) ,DIV(HI1769WS_Ch1_One_Decimal_Place_Int,10,HI1769WS_Ch1_One_Decimal_Place_Float) ][MUL(Hardy_HI1769WS_Ch1_Gross_Display_Float,100,HI1769WS_Ch1_Two_Decimal_Places_Int) ,DIV(HI1769WS_Ch1_Two_Decimal_Places_Int,100,HI1769WS_Ch1_Two_Decimals_Places_Float) ];
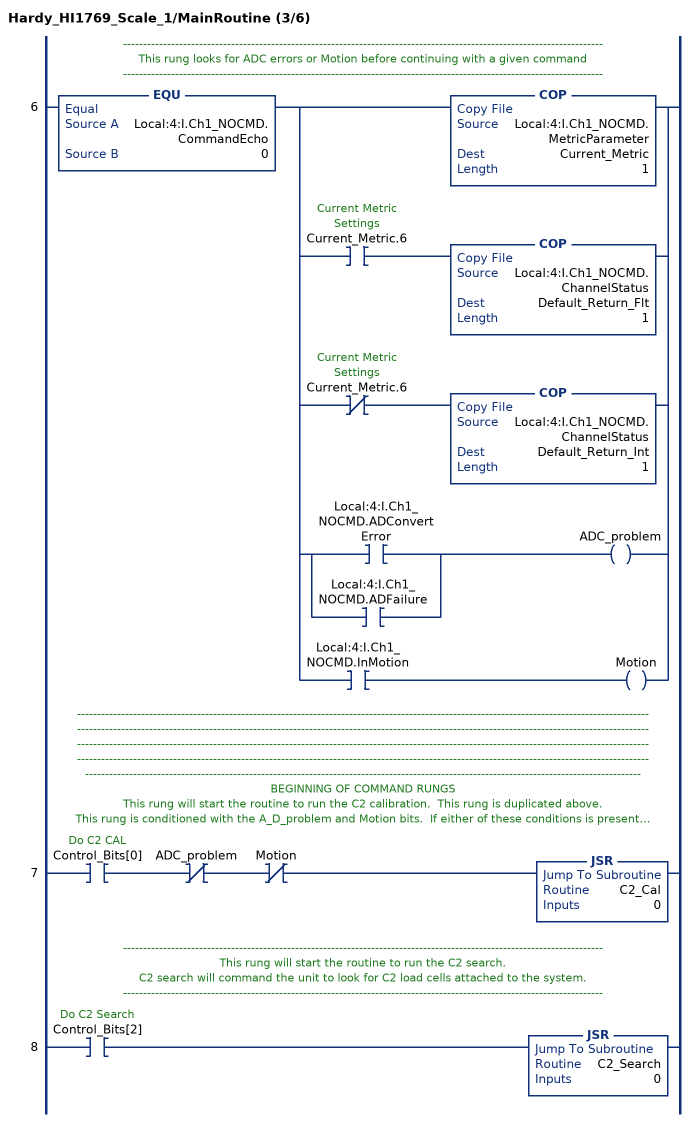
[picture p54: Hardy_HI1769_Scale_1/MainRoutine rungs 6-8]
   // ------------------------------------------------------------------------------------------------------------------------
   // This rung looks for ADC errors or Motion before continuing with a given command
   // ------------------------------------------------------------------------------------------------------------------------
   6: EQU(Local:4:I.Ch1_NOCMD.CommandEcho,0)[COP(Local:4:I.Ch1_NOCMD.MetricParameter,Current_Metric,1) ,XIC(Current_Metric.6) COP(Local:4:I.Ch1_NOCMD.ChannelStatus,Default_Return_Flt,1) ,XIO(Current_Metric.6) COP(Local:4:I.Ch1_NOCMD.ChannelStatus,Default_Return_Int,1) ,[XIC(Local:4:I.Ch1_NOCMD.ADConvertError) ,XIC(Local:4:I.Ch1_NOCMD.ADFailure) ] OTE(ADC_problem) ,XIC(Local:4:I.Ch1_NOCMD.InMotion) OTE(Motion) ];
   // ---------------------------------------------------------------------------------------------------------------------------------------------------------------------------------------------------------------------------------------------------------------------------------------------------------------------------------------------------------------------------------------------------------------------------------------------------------------------------------------------------------------------------------------------------------------------------------------------------------------------------------------------------------------------------------------------------------------------------------------
   // BEGINNING OF COMMAND RUNGS
   // This rung will start the routine to run the C2 calibration.  This rung is duplicated above.
   // This rung is conditioned with the A_D_problem and Motion bits.  If either of these conditions is present, the command would fail, so this will prevent the command from running if failure condition is present.
   // ------------------------------------------------------------------------------------------------------------------------
   7: XIC(Control_Bits[0])XIO(ADC_problem)XIO(Motion)JSR(C2_Cal,0);
   // ------------------------------------------------------------------------------------------------------------------------
   // This rung will start the routine to run the C2 search.
   // C2 search will command the unit to look for C2 load cells attached to the system.
   // ------------------------------------------------------------------------------------------------------------------------
   8: XIC(Control_Bits[2])JSR(C2_Search,0);
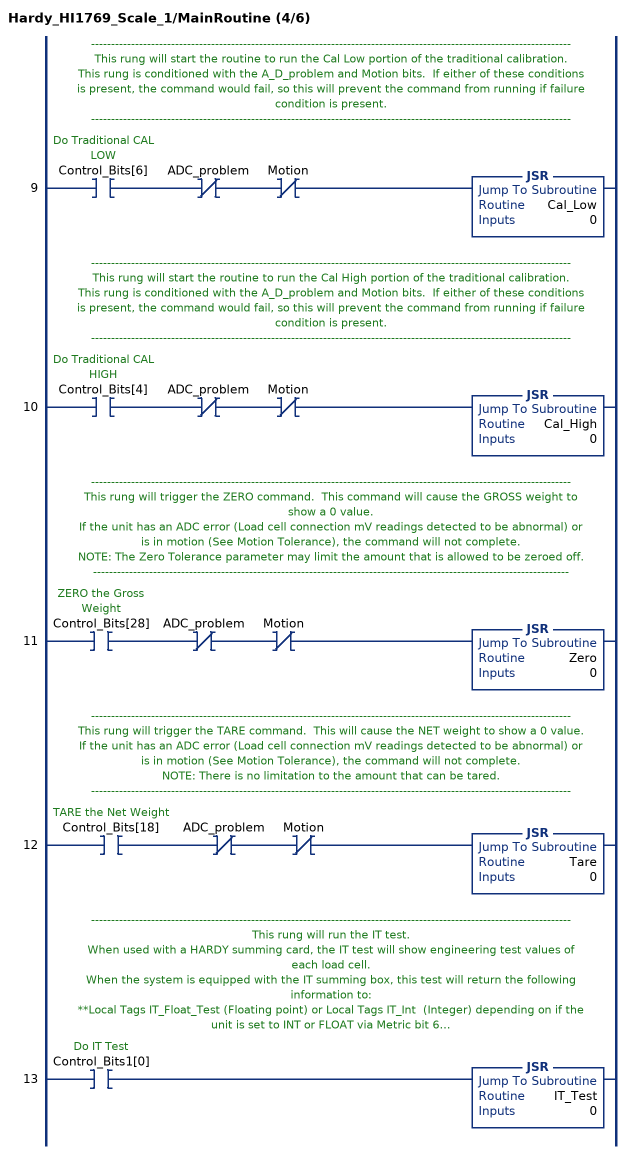
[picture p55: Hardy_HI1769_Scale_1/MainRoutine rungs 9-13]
   // ------------------------------------------------------------------------------------------------------------------------
   // This rung will start the routine to run the Cal Low portion of the traditional calibration.
   // This rung is conditioned with the A_D_problem and Motion bits.  If either of these conditions is present, the command would fail, so this will prevent the command from running if failure condition is present.
   // ------------------------------------------------------------------------------------------------------------------------
   9: XIC(Control_Bits[6])XIO(ADC_problem)XIO(Motion)JSR(Cal_Low,0);
   // ------------------------------------------------------------------------------------------------------------------------
   // This rung will start the routine to run the Cal High portion of the traditional calibration.
   // This rung is conditioned with the A_D_problem and Motion bits.  If either of these conditions is present, the command would fail, so this will prevent the command from running if failure condition is present.
   // ------------------------------------------------------------------------------------------------------------------------
   10: XIC(Control_Bits[4])XIO(ADC_problem)XIO(Motion)JSR(Cal_High,0);
   // ------------------------------------------------------------------------------------------------------------------------
   // This rung will trigger the ZERO command.  This command will cause the GROSS weight to show a 0 value.
   // If the unit has an ADC error (Load cell connection mV readings detected to be abnormal) or is in motion (See Motion Tolerance), the command will not complete.
   // NOTE: The Zero Tolerance parameter may limit the amount that is allowed to be zeroed off.
   // -----------------------------------------------------------------------------------------------------------------------
   11: XIC(Control_Bits[28])XIO(ADC_problem)XIO(Motion)JSR(Zero,0);
   // ------------------------------------------------------------------------------------------------------------------------
   // This rung will trigger the TARE command.  This will cause the NET weight to show a 0 value.
   // If the unit has an ADC error (Load cell connection mV readings detected to be abnormal) or is in motion (See Motion Tolerance), the command will not complete.
   // NOTE: There is no limitation to the amount that can be tared.
   // ------------------------------------------------------------------------------------------------------------------------
   12: XIC(Control_Bits[18])XIO(ADC_problem)XIO(Motion)JSR(Tare,0);
   // ------------------------------------------------------------------------------------------------------------------------
   // This rung will run the IT test.
   // When used with a HARDY summing card, the IT test will show engineering test values of each load cell.
   // When the system is equipped with the IT summing box, this test will return the following information to:
   // **Local Tags IT_Float_Test (Floating point) or Local Tags IT_Int  (Integer) depending on if the unit is set to INT or FLOAT via Metric bit 6.
   // The IT test may take up to 30 seconds and weight readings may fluctuate.
   // ------------------------------------------------------------------------------------------------------------------------
   13: XIC(Control_Bits1[0])JSR(IT_Test,0);
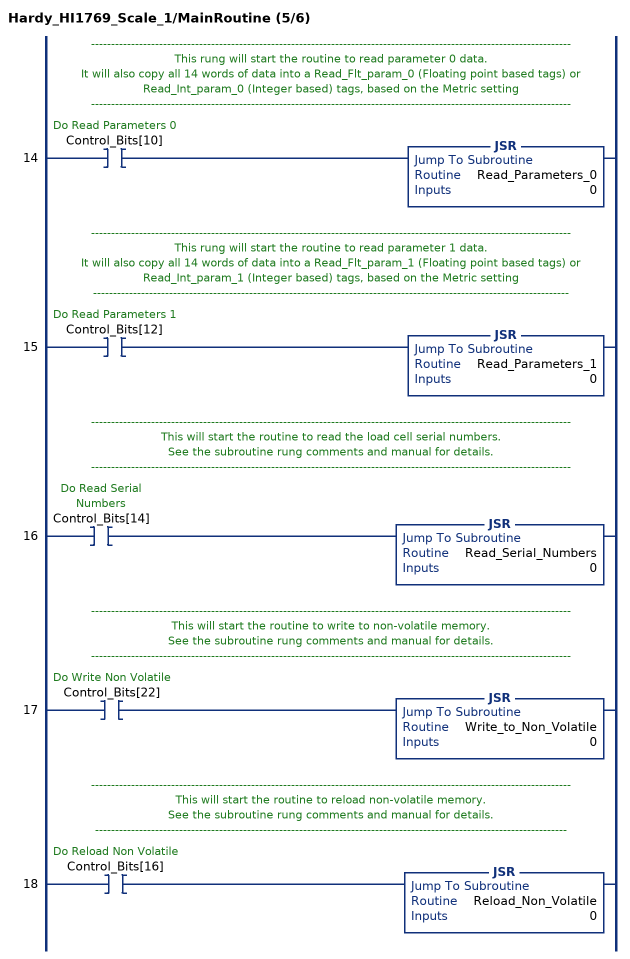
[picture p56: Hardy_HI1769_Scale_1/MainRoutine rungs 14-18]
   // ------------------------------------------------------------------------------------------------------------------------
   // This rung will start the routine to read parameter 0 data.
   // It will also copy all 14 words of data into a Read_Flt_param_0 (Floating point based tags) or Read_Int_param_0 (Integer based) tags, based on the Metric setting
   // ------------------------------------------------------------------------------------------------------------------------
   14: XIC(Control_Bits[10])JSR(Read_Parameters_0,0);
   // ------------------------------------------------------------------------------------------------------------------------
   // This rung will start the routine to read parameter 1 data.
   // It will also copy all 14 words of data into a Read_Flt_param_1 (Floating point based tags) or Read_Int_param_1 (Integer based) tags, based on the Metric setting
   // -----------------------------------------------------------------------------------------------------------------------
   15: XIC(Control_Bits[12])JSR(Read_Parameters_1,0);
   // ------------------------------------------------------------------------------------------------------------------------
   // This will start the routine to read the load cell serial numbers.
   // See the subroutine rung comments and manual for details.
   // ------------------------------------------------------------------------------------------------------------------------
   16: XIC(Control_Bits[14])JSR(Read_Serial_Numbers,0);
   // ------------------------------------------------------------------------------------------------------------------------
   // This will start the routine to write to non-volatile memory.
   // See the subroutine rung comments and manual for details.
   // ------------------------------------------------------------------------------------------------------------------------
   17: XIC(Control_Bits[22])JSR(Write_to_Non_Volatile,0);
   // ------------------------------------------------------------------------------------------------------------------------
   // This will start the routine to reload non-volatile memory.
   // See the subroutine rung comments and manual for details.
   // ----------------------------------------------------------------------------------------------------------------------
   18: XIC(Control_Bits[16])JSR(Reload_Non_Volatile,0);
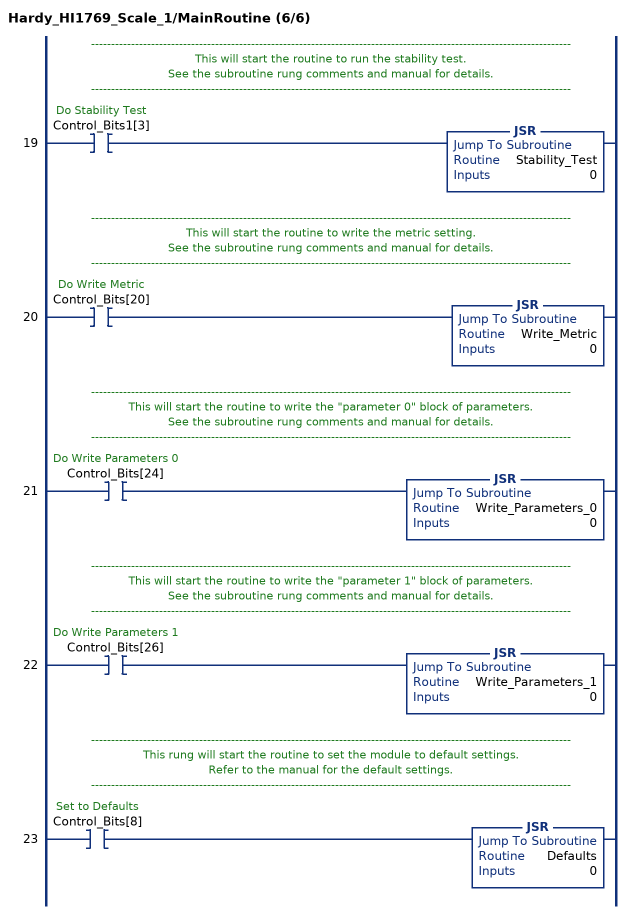
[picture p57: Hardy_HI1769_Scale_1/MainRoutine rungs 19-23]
   // ------------------------------------------------------------------------------------------------------------------------
   // This will start the routine to run the stability test.
   // See the subroutine rung comments and manual for details.
   // ------------------------------------------------------------------------------------------------------------------------
   19: XIC(Control_Bits1[3])JSR(Stability_Test,0);
   // ------------------------------------------------------------------------------------------------------------------------
   // This will start the routine to write the metric setting.
   // See the subroutine rung comments and manual for details.
   // ------------------------------------------------------------------------------------------------------------------------
   20: XIC(Control_Bits[20])JSR(Write_Metric,0);
   // ------------------------------------------------------------------------------------------------------------------------
   // This will start the routine to write the "parameter 0" block of parameters.
   // See the subroutine rung comments and manual for details.
   // ------------------------------------------------------------------------------------------------------------------------
   21: XIC(Control_Bits[24])JSR(Write_Parameters_0,0);
   // ------------------------------------------------------------------------------------------------------------------------
   // This will start the routine to write the "parameter 1" block of parameters.
   // See the subroutine rung comments and manual for details.
   // ------------------------------------------------------------------------------------------------------------------------
   22: XIC(Control_Bits[26])JSR(Write_Parameters_1,0);
   // ------------------------------------------------------------------------------------------------------------------------
   // This rung will start the routine to set the module to default settings.
   // Refer to the manual for the default settings.
   // ------------------------------------------------------------------------------------------------------------------------
   23: XIC(Control_Bits[8])JSR(Defaults,0);
END_ROUTINE
